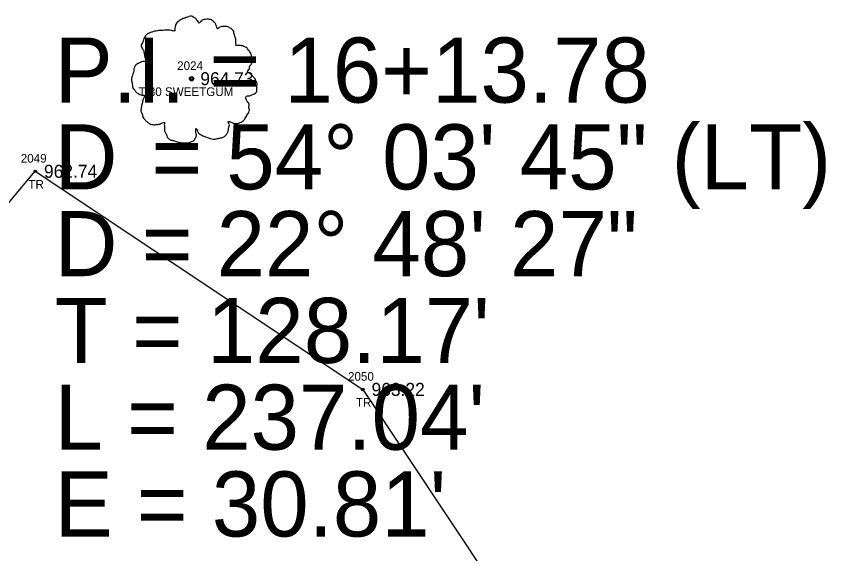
# Model space of a CAD drawing. Extents: x 1528109 to 1531398, y 1157799 to 1162548.
# Drawn here: x 1530489.6 to 1530582.9, y 1159141 to 1159203 of the extents above; entities that cross this region are included whole.
import ezdxf

# ---------------------------------------------------------------- set-up
doc = ezdxf.new("R2010")
doc.units = 0
for name, color, linetype in [('RD_EX_TX_VEG_ELEV', 7, 'Continuous'), ('RD_EX_VEG', 7, 'Continuous'), ('RD_EX_VEG_txCode', 7, 'Continuous'), ('RD_HC_Data', 7, 'Continuous'), ('RD_SMD_Locator', 7, 'Continuous')]:
    doc.layers.add(name, color=color, linetype=linetype)

msp = doc.modelspace()

# ---------------------------------------------------------------- linework, layer by layer
at = {"layer": 'RD_EX_VEG'}
msp.add_lwpolyline([(1530554.361, 1159122.561), (1530525.644, 1159099.661), (1530455.01, 1159141.078), (1530491.774, 1159185.083), (1530529.517, 1159159.951), (1530554.361, 1159122.561)], dxfattribs=at)
for centre, radius in [((1530509.79, 1159195.758), 0.25), ((1530509.778, 1159195.739), 0.0001)]:
    msp.add_circle(centre, radius, dxfattribs=at)
for points in [[(1530509.922, 1159202.925), (1530509.622, 1159202.95), (1530509.298, 1159202.85), (1530509.048, 1159202.751), (1530508.823, 1159202.676), (1530508.598, 1159202.576), (1530508.298, 1159202.401), (1530508.073, 1159202.201), (1530507.948, 1159201.951), (1530507.898, 1159201.726), (1530507.848, 1159201.451), (1530507.848, 1159201.276), (1530507.723, 1159201.251), (1530507.573, 1159201.276), (1530507.323, 1159201.351), (1530507.073, 1159201.351), (1530506.824, 1159201.351), (1530506.474, 1159201.326), (1530506.124, 1159201.326), (1530505.849, 1159201.276), (1530505.524, 1159201.226), (1530505.149, 1159201.101), (1530504.799, 1159200.976), (1530504.5, 1159200.726), (1530504.25, 1159200.252), (1530504.125, 1159199.902), (1530503.975, 1159199.652), (1530504.125, 1159199.202), (1530504.3, 1159198.852), (1530504.325, 1159198.652), (1530504.4, 1159198.228), (1530504.5, 1159198.003), (1530504.625, 1159197.803), (1530504.55, 1159197.778), (1530504.175, 1159197.728), (1530503.875, 1159197.628), (1530503.45, 1159197.403), (1530503.225, 1159197.178), (1530503.125, 1159196.853), (1530503.1, 1159196.503), (1530503, 1159196.303), (1530502.925, 1159196.028), (1530502.9, 1159195.953), (1530502.85, 1159195.629), (1530502.95, 1159195.179), (1530502.975, 1159194.829), (1530503.1, 1159194.604), (1530503.25, 1159194.429), (1530503.425, 1159194.179), (1530503.825, 1159193.954), (1530504.15, 1159193.854), (1530504.35, 1159193.829), (1530504.175, 1159193.33), (1530504.125, 1159192.98), (1530504, 1159192.58), (1530504, 1159192.505), (1530503.95, 1159192.03), (1530504.1, 1159191.705), (1530504.175, 1159191.331), (1530504.35, 1159191.106), (1530504.625, 1159190.806), (1530504.949, 1159190.581), (1530505.449, 1159190.456), (1530505.849, 1159190.481), (1530506.424, 1159190.656), (1530506.674, 1159190.731), (1530506.649, 1159190.556), (1530506.674, 1159190.181), (1530506.674, 1159189.756), (1530506.824, 1159189.431), (1530506.924, 1159189.156), (1530507.073, 1159188.907), (1530507.398, 1159188.682), (1530507.798, 1159188.607), (1530508.223, 1159188.457), (1530508.673, 1159188.382), (1530509.173, 1159188.357), (1530509.772, 1159188.507), (1530510.047, 1159188.632), (1530510.147, 1159188.807), (1530510.347, 1159189.181), (1530510.297, 1159189.406), (1530510.322, 1159190.006), (1530510.422, 1159189.831), (1530510.597, 1159189.481), (1530511.097, 1159189.181), (1530511.497, 1159189.007), (1530511.971, 1159188.857), (1530512.271, 1159188.782), (1530512.746, 1159188.857), (1530513.121, 1159188.932), (1530513.496, 1159189.057), (1530513.796, 1159189.331), (1530513.97, 1159189.606), (1530514.02, 1159189.881), (1530514.095, 1159190.256), (1530514.145, 1159190.431)], [(1530514.145, 1159190.431), (1530514.07, 1159190.606), (1530514.02, 1159190.856), (1530514.095, 1159190.831), (1530514.27, 1159190.781), (1530514.545, 1159190.656), (1530514.77, 1159190.581), (1530515.095, 1159190.606), (1530515.37, 1159190.706), (1530515.82, 1159190.981), (1530516.095, 1159191.455), (1530516.369, 1159191.855), (1530516.444, 1159192.18), (1530516.394, 1159192.405), (1530516.369, 1159192.905), (1530516.169, 1159193.155), (1530516.119, 1159193.28), (1530516.02, 1159193.679), (1530516.095, 1159193.729), (1530516.369, 1159193.779), (1530516.744, 1159193.904), (1530517.019, 1159194.029), (1530517.244, 1159194.204), (1530517.319, 1159194.429), (1530517.294, 1159194.829), (1530517.344, 1159195.229), (1530517.269, 1159195.379), (1530517.169, 1159195.529), (1530517.094, 1159195.729), (1530516.944, 1159195.878), (1530516.844, 1159196.028), (1530516.744, 1159196.128), (1530516.619, 1159196.278), (1530516.444, 1159196.403), (1530516.294, 1159196.453), (1530516.244, 1159196.603), (1530516.394, 1159196.803), (1530516.444, 1159196.903), (1530516.469, 1159197.128), (1530516.694, 1159197.478), (1530516.744, 1159197.878), (1530516.694, 1159198.302), (1530516.644, 1159198.577), (1530516.494, 1159198.852), (1530516.294, 1159199.102), (1530516.169, 1159199.277), (1530515.995, 1159199.402), (1530515.67, 1159199.527), (1530515.42, 1159199.577), (1530515.07, 1159199.577), (1530514.87, 1159199.627), (1530514.895, 1159199.677), (1530514.895, 1159199.827), (1530514.895, 1159200.102), (1530514.82, 1159200.551), (1530514.67, 1159201.051), (1530514.67, 1159201.076), (1530514.57, 1159201.326), (1530514.345, 1159201.526), (1530514.17, 1159201.626), (1530513.97, 1159201.751), (1530513.721, 1159201.776), (1530513.421, 1159201.776), (1530513.146, 1159201.726), (1530512.946, 1159201.626), (1530512.771, 1159201.501), (1530512.696, 1159201.651), (1530512.596, 1159201.951), (1530512.546, 1159202.101), (1530512.396, 1159202.276), (1530512.171, 1159202.476), (1530511.721, 1159202.601), (1530511.097, 1159202.526), (1530510.797, 1159202.326), (1530510.647, 1159202.151), (1530510.597, 1159202.276), (1530510.397, 1159202.476), (1530510.297, 1159202.651), (1530510.122, 1159202.776), (1530509.972, 1159202.875), (1530509.872, 1159202.925)]]:
    msp.add_spline(points, degree=3, dxfattribs=at)
at = {"layer": 'RD_SMD_Locator'}
for centre in [(1530509.79, 1159195.758), (1530491.774, 1159185.083), (1530529.517, 1159159.951)]:
    msp.add_circle(centre, 0.15, dxfattribs=at)

# ---------------------------------------------------------------- texts
at = {"layer": 'RD_EX_TX_VEG_ELEV'}
for s, p in [('964.73', (1530510.79, 1159195.008)), ('962.74', (1530492.774, 1159184.333)), ('963.22', (1530530.517, 1159159.201))]:
    msp.add_text(s, height=1.5, dxfattribs=at).set_placement(p)
at = {"layer": 'RD_EX_VEG_txCode'}
for s, p in [('2024', (1530508.121, 1159196.758)), ('T 30 SWEETGUM', (1530503.672, 1159193.758)), ('2049', (1530490.104, 1159186.083)), ('TR', (1530490.978, 1159183.083)), ('2050', (1530527.808, 1159160.951)), ('TR', (1530528.721, 1159157.951))]:
    msp.add_text(s, height=1, dxfattribs=at).set_placement(p)
at = {"layer": 'RD_HC_Data'}
for s, p in [('P.I. = 16+13.78', (1530494, 1159193)), ('D', (1530494, 1159183)), ('    = 54%%d 03\' 45" (LT)', (1530494, 1159183)), ('D = 22%%d 48\' 27"', (1530494, 1159173)), ("T = 128.17'", (1530494, 1159163)), ("L = 237.04'", (1530494, 1159153)), ("E = 30.81'", (1530494, 1159143))]:
    msp.add_text(s, height=7.5, dxfattribs=at).set_placement(p)

doc.saveas('drawing.dxf')
